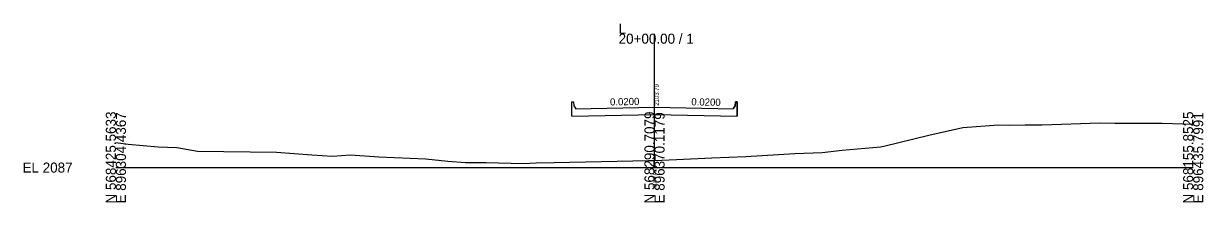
# Model space of a CAD drawing. Extents: x -26 to 1603, y -10 to 13527.
# Drawn here: x -25.7 to 302.8, y 7490.3 to 7540.1 of the extents above; entities that cross this region are included whole.
import ezdxf

# ---------------------------------------------------------------- set-up
doc = ezdxf.new("R2010")
doc.units = 0
for name, color, linetype in [('Default', 7, 'Continuous'), ('Exist XS Center Line Elevation Label', 7, 'Continuous'), ('Exist XS Ground Line', 7, 'Continuous'), ('Old_Level_63', 7, 'Continuous'), ('Prop XS Bridge', 7, 'Continuous'), ('Prop XSC Text', 7, 'Continuous')]:
    doc.layers.add(name, color=color, linetype=linetype)

msp = doc.modelspace()

# ---------------------------------------------------------------- linework, layer by layer
at = {"layer": 'Exist XS Ground Line'}
for p, q in [((226.36, 7508.99), (235.88, 7511.13)), ((235.88, 7511.13), (245.82, 7511.86)), ((245.82, 7511.86), (248.79, 7511.82)), ((248.79, 7511.82), (253.18, 7511.89)), ((253.18, 7511.89), (257.94, 7511.92)), ((257.94, 7511.92), (274.02, 7512.43)), ((274.02, 7512.43), (278.15, 7512.4)), ((278.15, 7512.4), (287.83, 7512.4)), ((287.83, 7512.4), (289.39, 7512.38)), ((289.39, 7512.38), (291.33, 7512.33)), ((291.33, 7512.33), (300, 7512.11)), ((213.84, 7506), (226.36, 7508.99)), ((0, 7506.96), (3.46, 7506.56)), ((3.46, 7506.56), (11.8, 7505.77)), ((11.8, 7505.77), (16.97, 7505.58)), ((16.97, 7505.58), (22.76, 7504.54)), ((22.76, 7504.54), (44.75, 7504.29)), ((44.75, 7504.29), (54.53, 7503.56)), ((175.45, 7503.05), (189.07, 7503.96)), ((189.07, 7503.96), (196.71, 7504.22)), ((196.71, 7504.22), (202.29, 7504.87)), ((202.29, 7504.87), (212.88, 7505.8)), ((212.88, 7505.8), (213.31, 7505.9)), ((213.31, 7505.9), (213.84, 7506)), ((54.53, 7503.56), (60.35, 7503.21)), ((60.35, 7503.21), (65.35, 7503.54)), ((65.35, 7503.54), (73.23, 7502.95)), ((73.23, 7502.95), (86.29, 7502.41)), ((86.29, 7502.41), (92.48, 7501.82)), ((92.48, 7501.82), (97.37, 7501.41)), ((97.37, 7501.41), (103.07, 7501.46)), ((103.07, 7501.46), (113.53, 7501.11)), ((113.53, 7501.11), (117.04, 7501.28)), ((117.04, 7501.28), (122.09, 7501.42)), ((122.09, 7501.42), (148.34, 7501.94)), ((148.34, 7501.94), (150, 7502.01)), ((150, 7502.01), (156.13, 7502.28)), ((156.13, 7502.28), (165.97, 7502.72)), ((165.97, 7502.72), (175.45, 7503.05))]:
    msp.add_line(p, q, dxfattribs=at)
at = {"layer": 'Old_Level_63'}
for p, q in [((150, 7500), (150, 7537.28)), ((0, 7500), (150, 7500)), ((150, 7500), (300, 7500))]:
    msp.add_line(p, q, dxfattribs=at)
at = {"layer": 'Prop XS Bridge'}
for p, q in [((126.96, 7518.3), (127.45, 7518.31)), ((126.96, 7518.3), (127.45, 7518.31)), ((126.96, 7518.3), (127.45, 7518.31)), ((126.96, 7514.33), (126.96, 7518.3)), ((126.96, 7514.42), (126.96, 7518.3)), ((126.96, 7515.97), (126.96, 7518.3)), ((127.45, 7518.31), (127.57, 7517.15)), ((127.45, 7518.31), (127.57, 7517.15)), ((127.45, 7518.31), (127.57, 7517.15)), ((127.57, 7517.15), (128, 7516.54)), ((127.57, 7517.15), (128, 7516.54)), ((127.57, 7517.15), (128, 7516.54)), ((172, 7516.54), (172.43, 7517.15)), ((172.43, 7517.15), (172, 7516.54)), ((172.43, 7517.15), (172.55, 7518.31)), ((172.55, 7518.31), (172.43, 7517.15)), ((172.55, 7518.31), (173.04, 7518.3)), ((173.04, 7518.3), (172.55, 7518.31)), ((173.04, 7518.3), (173.04, 7514.33)), ((173.04, 7514.52), (173.04, 7518.3)), ((126.96, 7514.33), (150.04, 7514.79)), ((128, 7516.35), (150, 7516.79)), ((128, 7516.54), (128, 7516.35)), ((128, 7516.54), (128, 7516.35)), ((128, 7516.54), (128, 7516.35)), ((149.96, 7514.79), (173.04, 7514.33)), ((150, 7516.79), (172, 7516.35)), ((172, 7516.35), (172, 7516.54)), ((172, 7516.54), (172, 7516.35))]:
    msp.add_line(p, q, dxfattribs=at)

# ---------------------------------------------------------------- texts
at = {"layer": 'Default'}
for rotation, p in [(1.1458, (137.62, 7517.28)), (358.8542, (160.23, 7517.33))]:
    msp.add_text('0.0200', height=2, rotation=rotation, dxfattribs=at).set_placement(p)
at = {"layer": 'Exist XS Center Line Elevation Label'}
msp.add_text('2089.01', height=1, rotation=90, dxfattribs=at).set_placement((150.5, 7494.44))
at = {"layer": 'Old_Level_63'}
for s, p in [('L', (140, 7537.28)), ('20+00.00 / 1', (140, 7534.48)), ('EL 2087', (-26, 7498.6))]:
    msp.add_text(s, height=2.8, dxfattribs=at).set_placement(p)
for s, p in [('N 568425.5633', (0, 7490)), ('E 896304.4367', (2.8, 7490)), ('N 568290.7079', (150, 7490)), ('E 896370.1179', (152.8, 7490)), ('N 568155.8525', (300, 7490)), ('E 896435.7991', (302.8, 7490))]:
    msp.add_text(s, height=2.8, rotation=90, dxfattribs=at).set_placement(p)
at = {"layer": 'Prop XSC Text'}
msp.add_text(' 2103.79', height=1.2, rotation=90, dxfattribs=at).set_placement((151.2, 7516.79))

doc.saveas('drawing.dxf')
